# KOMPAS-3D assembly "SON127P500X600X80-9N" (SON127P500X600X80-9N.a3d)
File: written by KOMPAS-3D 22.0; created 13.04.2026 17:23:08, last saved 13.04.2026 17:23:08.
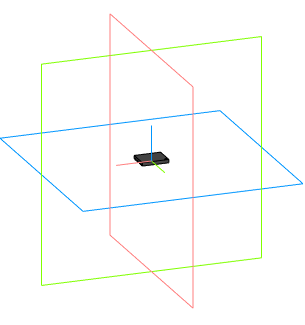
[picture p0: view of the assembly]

Document properties: Автор: Andrey; Полное имя файла: C:\Users\User1\Documents\SON127P500X600X80-9N.a3d

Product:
- Component [detail]: W25X40CLZPIG  | qty 1  | source file: W25X40CLZPIG.m3d
- Part/product: SON127P500X600X80-9N
    Комментарий: SON127P500X600X80-9N

Expressions: SON127P500X600X80-9N
Referenced files in C:\Users\User1\Documents\: W25X40CLZPIG.m3d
